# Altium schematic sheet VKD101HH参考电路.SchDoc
size A4
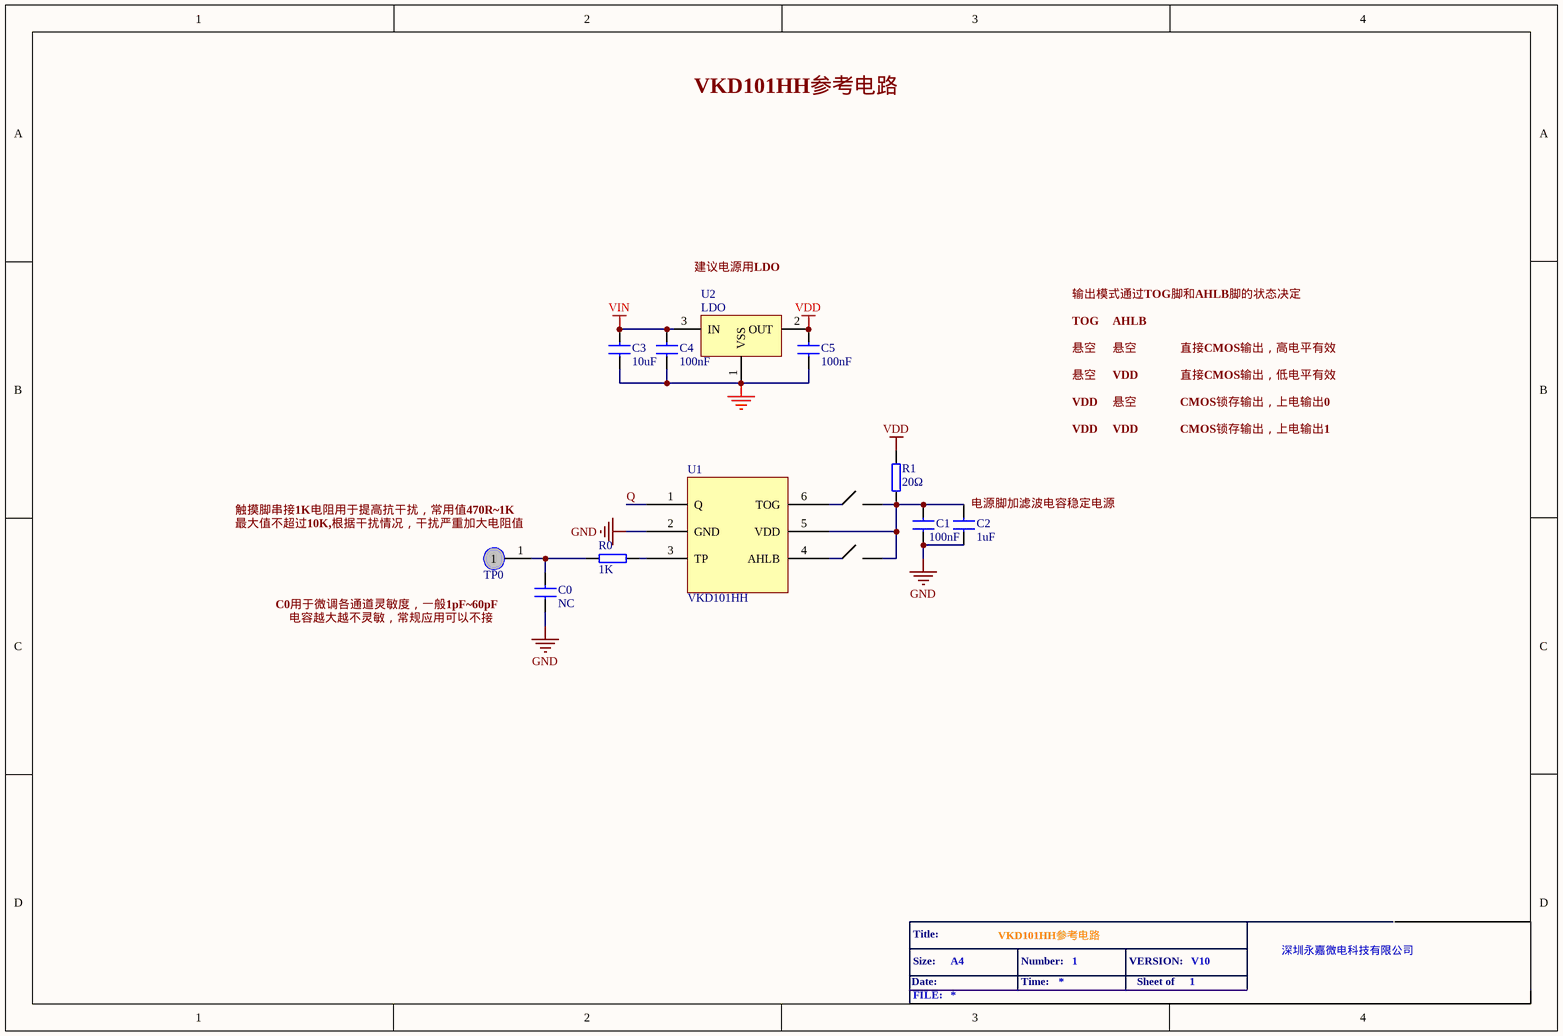
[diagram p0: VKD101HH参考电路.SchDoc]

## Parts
C0  value NC  [0603-C]  (hidden comment: 10uF)
C1  100nF  [0603-C]
C2  value 1uF  [0603-C]  (hidden comment: 10uF)
C3  10uF  [0805-C]
C4  100nF  [0805-C]
C5  100nF  [0805-C]
key0  单刀单掷开关  (value not drawn)
key1  单刀单掷开关  (value not drawn)
R0  1K  [0603-R]
R1  20Ω  [0603-R]
TP0  TPAD  [TP-PAD0]  (value not drawn)
U1  VKD101HH
U2  LDO  [SOT-23]

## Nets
GND: C0.1 C1.2 C2.2 C3.2 C4.2 C5.2 U1.2(GND) U2.1(VSS)
VDD: C5.1 R1.1 U2.2(OUT)
VIN: C3.1 C4.1 U2.3(IN)
Q: U1.1(Q)
NetC0_2: C0.2 R0.2 TP0.1
NetC1_1: C1.1 C2.1 R1.2 U1.5(VDD)
NetR0_1: R0.1 U1.3(TP)

Not connected (* = marked no-connect by the designer): U1 4(AHLB) 6(TOG)

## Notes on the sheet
- VKD101HH参考电路
- 建议电源用LDO
- 输出模式通过TOG脚和AHLB脚的状态决定
- TOG
- 悬空
- AHLB
- VDD
- 直接CMOS输出，高电平有效
- 直接CMOS输出，低电平有效
- CMOS锁存输出，上电输出0
- CMOS锁存输出，上电输出1
- 触摸脚串接1K电阻用于提高抗干扰，常用值470R
  K
- (near C2) 电源脚加滤波电容稳定电源
- 最大值不超过10K,根据干扰情况，干扰严重加大电阻值
- C0用于微调各通道灵敏度，一般1pF~60pF
- 电容越大越不灵敏，常规应用可以不接
- Date:
- Title:
- Size:
- A4
- Number:
- Time:
- 1
- VERSION:
- Sheet of
- V10
- 深圳永嘉微电科技有限公司
- FILE:

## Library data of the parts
C0-C5 = CAP: Capacitor
R0 R1 = RES: Resistor
TP0 = TPAD: TESTING
U2 = V6206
